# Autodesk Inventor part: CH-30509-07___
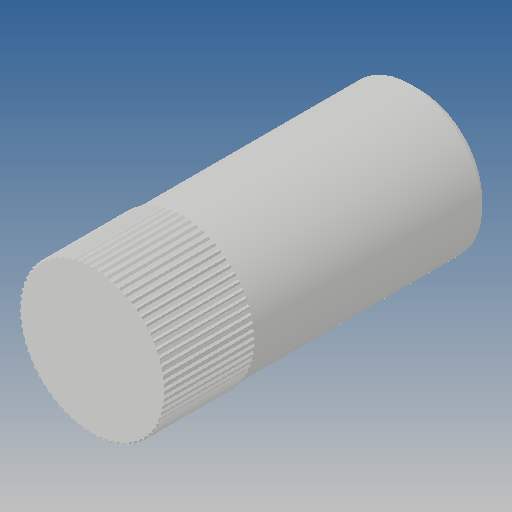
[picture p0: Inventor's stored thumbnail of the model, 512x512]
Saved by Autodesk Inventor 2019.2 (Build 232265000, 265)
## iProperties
Created: 2010-06
Part Number: CH-30509-07___
Material: Ogólny
Document SubType Name: Modeling
Designer: CADENGINEERING4
Density: 1 g/cm^3
Appearance: Domyślna
Author: CADENGINEERING4
Revision Number: ANY
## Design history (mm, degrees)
feature "NONE"
node "Bryła1"
